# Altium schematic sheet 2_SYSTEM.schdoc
size 426 x 302 mm; Symbol: Sheet_A3_Whycan; Device: Sheet_A3; @Project Name: Avaota A1 八核 AIoT 开发板; @Update Date: 2024-04-06; @Page No: 4; @Page Count: 13
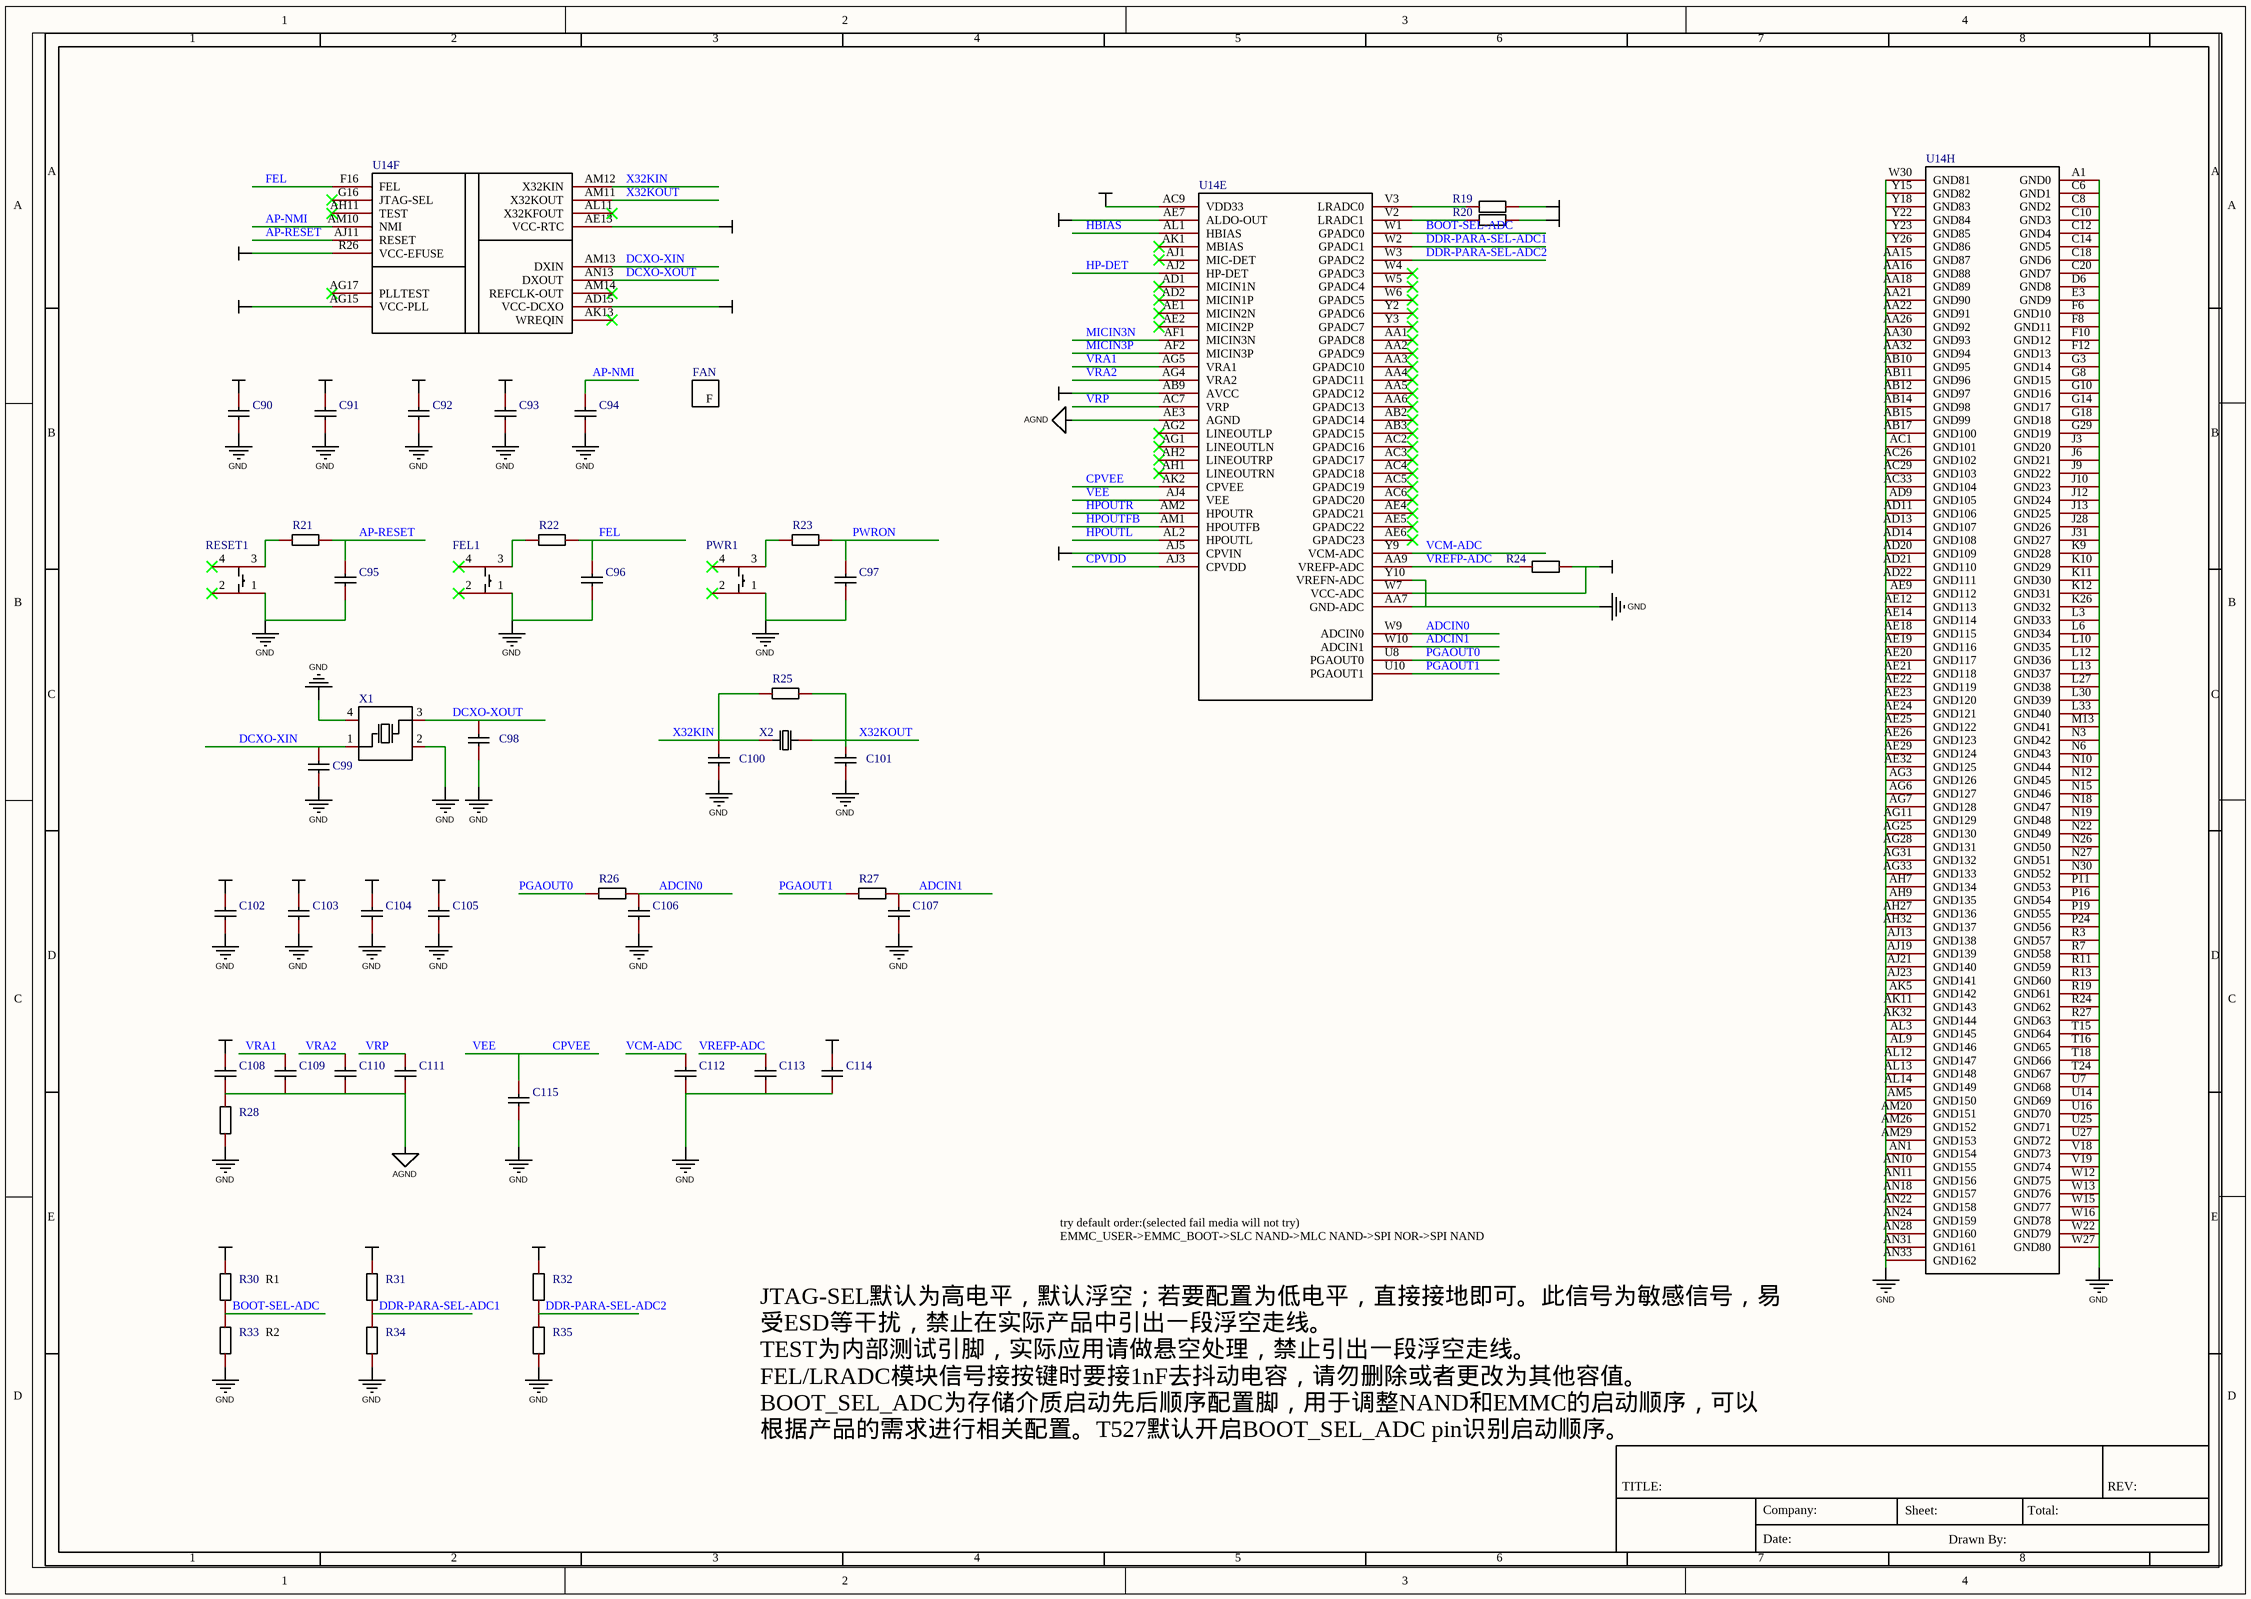
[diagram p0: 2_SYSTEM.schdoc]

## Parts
C90  GRM033R61A104KE15D  [c0201 nsk]  (value not drawn)
C91  GRM033R61A104KE15D  [c0201 nsk]  (value not drawn)
C92  GRM033R61A104KE15D  [c0201 nsk]  (value not drawn)
C93  GRM033R61A104KE15D  [c0201 nsk]  (value not drawn)
C94  GRM033R61A104KE15D  [c0201 nsk]  (value not drawn)
C95  GRM033R61A104KE15D  [c0201 nsk]  (value not drawn)
C96  GRM033R61A104KE15D  [c0201 nsk]  (value not drawn)
C97  GRM033R61A104KE15D  [c0201 nsk]  (value not drawn)
C98  0201CG220J500NT  [c0201 nsk]  (value not drawn)
C99  0201CG220J500NT  [c0201 nsk]  (value not drawn)
C100  0201CG220J500NT  [c0201 nsk]  (value not drawn)
C101  0201CG220J500NT  [c0201 nsk]  (value not drawn)
C102  GRM033R61A104KE15D  [c0201 nsk]  (value not drawn)
C103  GRM033R61A104KE15D  [c0201 nsk]  (value not drawn)
C104  GRM033R61A104KE15D  [c0201 nsk]  (value not drawn)
C105  GRM033R61A104KE15D  [c0201 nsk]  (value not drawn)
C106  GRM033R61A104KE15D  [c0201 nsk]  (value not drawn)
C107  GRM033R61A104KE15D  [c0201 nsk]  (value not drawn)
C108  GRM033R61A104KE15D  [c0201 nsk]  (value not drawn)
C109  GRM033R61A104KE15D  [c0201 nsk]  (value not drawn)
C110  GRM033R61A104KE15D  [c0201 nsk]  (value not drawn)
C111  GRM033R61A104KE15D  [c0201 nsk]  (value not drawn)
C112  GRM033R61A104KE15D  [c0201 nsk]  (value not drawn)
C113  GRM033R61A104KE15D  [c0201 nsk]  (value not drawn)
C114  GRM033R61A104KE15D  [c0201 nsk]  (value not drawn)
C115  GRM033R61A104KE15D  [c0201 nsk]  (value not drawn)
FAN  FAN2510  [FAN2510]  (value not drawn)
FEL1  YTSA016A0252501B  [SW-SMD_4P-L4.2-W3.4-P2.15-LS4.5-TL]  (value not drawn)
PWR1  YTSA016A0252501B  [SW-SMD_4P-L4.2-W3.4-P2.15-LS4.5-TL]  (value not drawn)
R19  Res_0201  [r0201 nsk]  (value not drawn)
R20  Res_0201  [r0201 nsk]  (value not drawn)
R21  Res_0201  [r0201 nsk]  (value not drawn)
R22  Res_0201  [r0201 nsk]  (value not drawn)
R23  Res_0201  [r0201 nsk]  (value not drawn)
R24  Res_0201  [r0201 nsk]  (value not drawn)
R25  Res_0201  [r0201 nsk]  (value not drawn)
R26  Res_0201  [r0201 nsk]  (value not drawn)
R27  Res_0201  [r0201 nsk]  (value not drawn)
R28  Res_0402  [R0402-NSK]  (value not drawn)
R30  Res_0201  [r0201 nsk]  (value not drawn)
R31  Res_0201  [r0201 nsk]  (value not drawn)
R32  Res_0201  [r0201 nsk]  (value not drawn)
R33  Res_0201  [r0201 nsk]  (value not drawn)
R34  Res_0201  [r0201 nsk]  (value not drawn)
R35  Res_0201  [r0201 nsk]  (value not drawn)
RESET1  YTSA016A0252501B  [SW-SMD_4P-L4.2-W3.4-P2.15-LS4.5-TL]  (value not drawn)
U14  T527  [T527-BGA664]  (value not drawn)  (parts E,F,H of 8)
X1  TAXM24M4ZDBCCT2T  [crystal-smd_4p-l2.0-w1.6-bl-nsk]  (value not drawn)
X2  Q13FC1350000400  [osc-smd_l3.2-w1.5 nsk]  (value not drawn)

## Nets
AGND: C108.1 C109.1 C110.1 C111.1 R28.2 U14.AE3(AGND)
ALDO-OUT: C103.2 U14.AE7(ALDO-OUT)
AVCC: C108.2 R19.2 R20.2 U14.AB9(AVCC)
CPVDD: C105.2 U14.AJ3(CPVDD)
CPVIN: C104.2 U14.AJ5(CPVIN)
GND: C90.1 C91.1 C92.1 C93.1 C94.1 C95.1 C96.1 C97.1 C98.1 C99.1 C100.1 C101.1 C102.1 C103.1 C104.1 C105.1 C106.1 C107.1 C112.1 C113.1 C114.1 C115.1 FEL1.1 PWR1.1 R28.1 R33.1 R34.1 R35.1 RESET1.1 U14.A1(GND0) U14.AA7(GND-ADC) U14.AA15(GND87) U14.AA16(GND88) U14.AA18(GND89) U14.AA21(GND90) U14.AA22(GND91) U14.AA26(GND92) U14.AA30(GND93) U14.AA32(GND94) U14.AB10(GND95) U14.AB11(GND96) U14.AB12(GND97) U14.AB14(GND98) U14.AB15(GND99) U14.AB17(GND100) U14.AC1(GND101) U14.AC26(GND102) U14.AC29(GND103) U14.AC33(GND104) U14.AD9(GND105) U14.AD11(GND106) U14.AD13(GND107) U14.AD14(GND108) U14.AD20(GND109) U14.AD21(GND110) U14.AD22(GND111) U14.AE9(GND112) U14.AE12(GND113) U14.AE14(GND114) U14.AE18(GND115) U14.AE19(GND116) U14.AE20(GND117) U14.AE21(GND118) U14.AE22(GND119) U14.AE23(GND120) U14.AE24(GND121) U14.AE25(GND122) U14.AE26(GND123) U14.AE29(GND124) U14.AE32(GND125) U14.AG3(GND126) U14.AG6(GND127) U14.AG7(GND128) U14.AG11(GND129) U14.AG25(GND130) U14.AG28(GND131) U14.AG31(GND132) U14.AG33(GND133) U14.AH7(GND134) U14.AH9(GND135) U14.AH27(GND136) U14.AH32(GND137) U14.AJ13(GND138) U14.AJ19(GND139) U14.AJ21(GND140) U14.AJ23(GND141) U14.AK5(GND142) U14.AK11(GND143) U14.AK32(GND144) U14.AL3(GND145) U14.AL9(GND146) U14.AL12(GND147) U14.AL13(GND148) U14.AL14(GND149) U14.AM5(GND150) U14.AM20(GND151) U14.AM26(GND152) U14.AM29(GND153) U14.AN1(GND154) U14.AN10(GND155) U14.AN11(GND156) U14.AN18(GND157) U14.AN22(GND158) U14.AN24(GND159) U14.AN28(GND160) U14.AN31(GND161) U14.AN33(GND162) U14.C6(GND1) U14.C8(GND2) U14.C10(GND3) U14.C12(GND4) U14.C14(GND5) U14.C18(GND6) U14.C20(GND7) U14.D6(GND8) U14.E3(GND9) U14.F6(GND10) U14.F8(GND11) U14.F10(GND12) U14.F12(GND13) U14.G3(GND14) U14.G8(GND15) U14.G10(GND16) U14.G14(GND17) U14.G18(GND18) U14.G29(GND19) U14.J3(GND20) U14.J6(GND21) U14.J9(GND22) U14.J10(GND23) U14.J12(GND24) U14.J13(GND25) U14.J28(GND26) U14.J31(GND27) U14.K9(GND28) U14.K10(GND29) U14.K11(GND30) U14.K12(GND31) U14.K26(GND32) U14.L3(GND33) U14.L6(GND34) U14.L10(GND35) U14.L12(GND36) U14.L13(GND37) U14.L27(GND38) U14.L30(GND39) U14.L33(GND40) U14.M13(GND41) U14.N3(GND42) U14.N6(GND43) U14.N10(GND44) U14.N12(GND45) U14.N15(GND46) U14.N18(GND47) U14.N19(GND48) U14.N22(GND49) U14.N26(GND50) U14.N27(GND51) U14.N30(GND52) U14.P11(GND53) U14.P16(GND54) U14.P19(GND55) U14.P24(GND56) U14.R3(GND57) U14.R7(GND58) U14.R11(GND59) U14.R13(GND60) U14.R19(GND61) U14.R24(GND62) U14.R27(GND63) U14.T15(GND64) U14.T16(GND65) U14.T18(GND66) U14.T24(GND67) U14.U7(GND68) U14.U14(GND69) U14.U16(GND70) U14.U25(GND71) U14.U27(GND72) U14.V18(GND73) U14.V19(GND74) U14.W12(GND75) U14.W13(GND76) U14.W15(GND77) U14.W16(GND78) U14.W22(GND79) U14.W27(GND80) U14.W30(GND81) U14.Y10(VREFN-ADC) U14.Y15(GND82) U14.Y18(GND83) U14.Y22(GND84) U14.Y23(GND85) U14.Y26(GND86) X1.2(GND) X1.4(GND)
VCC-ADC: C114.2 R24.2 R30.2 R31.2 R32.2 U14.W7(VCC-ADC)
VCC-DCXO: C90.2 U14.AD15(VCC-DCXO)
VCC-EFUSE: C91.2 U14.R26(VCC-EFUSE)
VCC-PLL: C93.2 U14.AG15(VCC-PLL)
VCC-RTC: C92.2 U14.AE13(VCC-RTC)
VDD33: C102.2 U14.AC9(VDD33)
ADCIN0: C106.2 R26.2 U14.W9(ADCIN0)
ADCIN1: C107.2 R27.2 U14.W10(ADCIN1)
AP-NMI: C94.2 U14.AM10(NMI)
AP-RESET: C95.2 R21.2 U14.AJ11(RESET)
BOOT-SEL-ADC: R30.1 R33.2 U14.W1(GPADC0)
CPVEE: C115.2 U14.AJ4(VEE) U14.AK2(CPVEE)  [also labelled VEE]
DCXO-XIN: C99.2 U14.AM13(DXIN) X1.1(OSC1)
DCXO-XOUT: C98.2 U14.AN13(DXOUT) X1.3(OSC2)
DDR-PARA-SEL-ADC1: R31.1 R34.2 U14.W2(GPADC1)
DDR-PARA-SEL-ADC2: R32.1 R35.2 U14.W3(GPADC2)
FEL: C96.2 R22.2 U14.F16(FEL)
HBIAS: U14.AL1(HBIAS)
HP-DET: U14.AJ2(HP-DET)
HPOUTFB: U14.AM1(HPOUTFB)
HPOUTL: U14.AL2(HPOUTL)
HPOUTR: U14.AM2(HPOUTR)
MICIN3N: U14.AF1(MICIN3N)
MICIN3P: U14.AF2(MICIN3P)
PGAOUT0: R26.1 U14.U8(PGAOUT0)
PGAOUT1: R27.1 U14.U10(PGAOUT1)
PWRON: C97.2 R23.2
VCM-ADC: C112.2 U14.Y9(VCM-ADC)
VRA1: C109.2 U14.AG5(VRA1)
VRA2: C110.2 U14.AG4(VRA2)
VREFP-ADC: C113.2 R24.1 U14.AA9(VREFP-ADC)
VRP: C111.2 U14.AC7(VRP)
X32KIN: C100.2 R25.1 U14.AM12(X32KIN) X2.1
X32KOUT: C101.2 R25.2 U14.AM11(X32KOUT) X2.2
NetFEL1_3: FEL1.3 R22.1
NetPWR1_3: PWR1.3 R23.1
NetR19_1: R19.1 U14.V3(LRADC0)
NetR20_1: R20.1 U14.V2(LRADC1)
NetR21_1: R21.1 RESET1.3

Not connected (* = marked no-connect by the designer): FEL1 2* 4*; PWR1 2* 4*; RESET1 2* 4*; U14 AA1(GPADC8)* AA2(GPADC9)* AA3(GPADC10)* AA4(GPADC11)* AA5(GPADC12)* AA6(GPADC13)* AB2(GPADC14)* AB3(GPADC15)* AC2(GPADC16)* AC3(GPADC17)* AC4(GPADC18)* AC5(GPADC19)* AC6(GPADC20)* AD1(MICIN1N)* AD2(MICIN1P)* AE1(MICIN2N)* AE2(MICIN2P)* AE4(GPADC21)* AE5(GPADC22)* AE6(GPADC23)* AG1(LINEOUTLN)* AG2(LINEOUTLP)* AG17(PLLTEST)* AH1(LINEOUTRN)* AH2(LINEOUTRP)* AH11(TEST)* AJ1(MIC-DET)* AK1(MBIAS)* AK13(WREQIN)* AL11(X32KFOUT)* AM14(REFCLK-OUT)* G16(JTAG-SEL)* W4(GPADC3)* W5(GPADC4)* W6(GPADC5)* Y2(GPADC6)* Y3(GPADC7)*

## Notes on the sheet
- try default order:(selected fail media will not try)
  EMMC_USER->EMMC_BOOT->SLC NAND->MLC NAND->SPI NOR->SPI NAND
- R1
- JTAG-SEL默认为高电平，默认浮空；若要配置为低电平，直接接地即可。此信号为敏感信号，易
  受ESD等干扰，禁止在实际产品中引出一段浮空走线。
  TEST为内部测试引脚，实际应用请做悬空处理，禁止引出一段浮空走线。
  FEL/LRADC模块信号接按键时要接1nF去抖动电容，请勿删除或者更改为其他容值。
  BOOT_SEL_ADC为存储介质启动先后顺序配置脚，用于调整NAND和EMMC的启动顺序，可以
  根据产品的需求进行相关配置。T527默认开启BOOT_SEL_ADC pin识别启动顺序。
- R2

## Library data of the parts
C90-C93 C102 = GRM033R61A104KE15D: Manufacturer: muRata(村田); Value: 100nF; Add into BOM: yes; Tolerance: ±10%; Voltage Rated: 10V; Temperature Coefficient: X5R; Description: 容值:100nF;精度:±10%;额定电压:10V;材质(温度系数):X5R;
C94-C97 C107 = GRM033R61A104KE15D: Manufacturer: muRata(村田); Value: 1nF; Add into BOM: yes; Tolerance: ±10%; Voltage Rated: 10V; Temperature Coefficient: X5R; Description: 容值:100nF;精度:±10%;额定电压:10V;材质(温度系数):X5R;
C98-C101 = 0201CG220J500NT: Manufacturer: FH(风华); Value: 22pF; Add into BOM: yes; Tolerance: ±5%; Voltage Rated: 50V; Temperature Coefficient: C0G; Description: 容值:22pF;精度:±5%;额定电压:50V;材质(温度系数):C0G;
C103-C105 C108 C113-C115 = GRM033R61A104KE15D: Manufacturer: muRata(村田); Value: 2.2uF; Add into BOM: yes; Tolerance: ±10%; Voltage Rated: 10V; Temperature Coefficient: X5R; Description: 容值:100nF;精度:±10%;额定电压:10V;材质(温度系数):X5R;
C106 = GRM033R61A104KE15D: Manufacturer: muRata(村田); Value: 10nF; Add into BOM: yes; Tolerance: ±10%; Voltage Rated: 10V; Temperature Coefficient: X5R; Description: 容值:100nF;精度:±10%;额定电压:10V;材质(温度系数):X5R;
C109-C112 = GRM033R61A104KE15D: Manufacturer: muRata(村田); Value: 470nF; Add into BOM: yes; Tolerance: ±10%; Voltage Rated: 10V; Temperature Coefficient: X5R; Description: 容值:100nF;精度:±10%;额定电压:10V;材质(温度系数):X5R;
FAN = FAN2510: Add into BOM: yes
FEL1 PWR1 RESET1 = YTSA016A0252501B: Manufacturer: DGBZ(东莞博众); Add into BOM: yes; Circuit: 单刀单掷; Actuator Style: 椭圆形按钮; Operating Force: 250gf; Switch Length: 4.2mm; Switch Width: 3.4mm; Switch Height: 2.5mm; Strike Gundam: 不带; Contact Current: 50mA; Voltage Rating (DC): 12V; Insulation Resistance: 100MΩ; Actuator/Cap Color: 白色; Pin Style: J型引脚; Mechanical Life: 10万次; Description: 电路结构:单刀单掷;按钮形状:椭圆形按钮;作用力:250gf;安装方式:立贴;开关长度:4.2mm;开关宽度:3.4mm;开关高度:2.5mm;带支架:不带;触点电流:50mA;额定电压(DC):12V;绝缘电阻:100MΩ;机械寿命:10万次;
R19 R20 R30 R32 R34 = Res_0201: Symbol: 电阻; Convert to PCB: yes; Value: 10K
R21-R23 R26 R27 = Res_0201: Symbol: 电阻; Convert to PCB: yes; Value: 1K
R24 = Res_0201: Symbol: 电阻; Convert to PCB: yes; Value: 0
R25 = Res_0201: Symbol: 电阻; Convert to PCB: yes; Value: 10M
R28 = Res_0402: Symbol: 电阻; Convert to PCB: yes; Value: 0
R31 R35 = Res_0201: Symbol: 电阻; Convert to PCB: yes; Value: NC
R33 = Res_0201: Symbol: 电阻; Convert to PCB: yes; Value: 3.9K
U14 = T527: Add into BOM: yes; SWAP_INFO: (S1+S2+S3+S4+S5+S6+S7+S8+S9); SPLIT_INST: TRUE; Description: Allwinner T527 SoC
X1 = TAXM24M4ZDBCCT2T: Manufacturer: YJX(雅晶鑫); Add into BOM: yes; Crystal Type: 贴片无源晶振; Value: 24MHz; Normal temperature Frequency Tolerance: ±20ppm; Load Capacitance: 10pF; Frequency Stability(Full temperature range): ±15ppm; Equivalent Series Resistance (ESR): 80Ω; Description: 晶振类型:贴片无源晶振;频率:24MHz;常温频差:±20ppm;负载电容:10pF;频率稳定度(全温):±15ppm;
X2 = Q13FC1350000400: Manufacturer: EPSON(爱普生); Add into BOM: yes; Crystal Type: 贴片无源晶振; Value: 32.768kHz; Load Capacitance: 12.5pF; Equivalent Series Resistance (ESR): 70kΩ; Frequency Tolerance: ±20ppm; Description: 频率:32.768kHz;负载电容:12.5pF;频率公差:±20ppm;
